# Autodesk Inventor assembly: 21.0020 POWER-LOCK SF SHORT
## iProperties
Created: 2012-06
Part Number: 21.0020 POWER-LOCK SF SHORT
Document SubType Name: Assembly
Designer: Administrator
Author: Administrator
